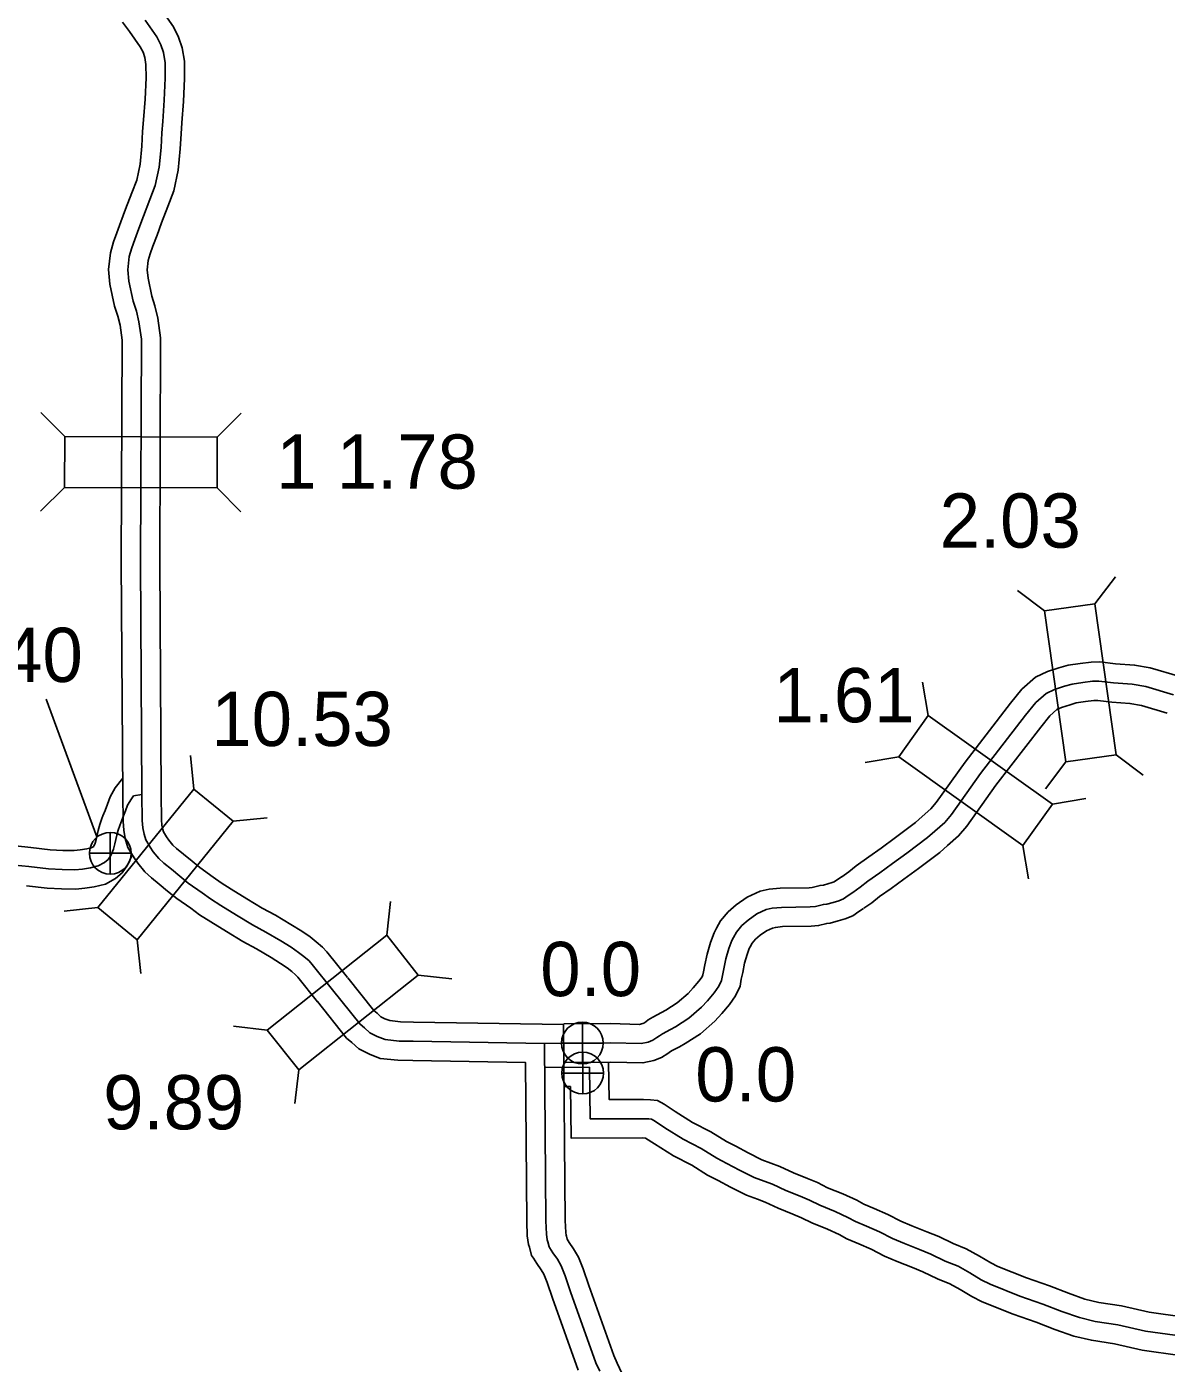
# Model space of a CAD drawing. Extents: x -83719 to 153526, y -11835 to 11446.
# Drawn here: x -2013.5 to -1717.5, y 1861.1 to 2208 of the extents above; entities that cross this region are included whole.
import ezdxf

# ---------------------------------------------------------------- set-up
doc = ezdxf.new("R2010")
doc.units = 0
for name, color, linetype in [('Level 10', 7, 'Continuous'), ('Level 11', 7, 'Continuous'), ('Level 20', 7, 'Continuous'), ('Level 25', 7, 'Continuous'), ('Level 26', 7, 'Continuous'), ('Level 58', 7, 'Continuous'), ('Level 59', 7, 'Continuous')]:
    doc.layers.add(name, color=color, linetype=linetype)

msp = doc.modelspace()

# ---------------------------------------------------------------- linework, layer by layer
at = {"layer": 'Level 10'}
for points in [[(-1978.66, 2212.67), (-1975.38, 2207.95), (-1974.03, 2205.31), (-1973.07, 2202.54), (-1972.5, 2199.05), (-1972.48, 2194.56), (-1972.74, 2188.64), (-1973.17, 2183.08), (-1973.39, 2180.2), (-1973.58, 2176.3), (-1974.14, 2170.79), (-1975.26, 2165.4), (-1976.79, 2161.37), (-1978.44, 2157.12), (-1979.62, 2153.9), (-1980.67, 2151.06), (-1981.41, 2149.05), (-1981.9, 2147.37), (-1982.18, 2144.93), (-1981.96, 2142.73), (-1980.98, 2138.1), (-1980.17, 2135.61), (-1979.39, 2132.4), (-1978.69, 2127.29), (-1978.9, 2069.17), (-1978.53, 2008.78), (-1978.45, 2002.2), (-1978.34, 2000.79), (-1978.13, 1999.64), (-1977.96, 1999.05), (-1977.19, 1997.79), (-1976.58, 1996.9), (-1975.55, 1995.63), (-1974.6, 1994.78), (-1972.71, 1993.24), (-1970.53, 1991.44), (-1968.49, 1989.77), (-1965.02, 1987.34), (-1962.96, 1985.83), (-1960.39, 1984.23), (-1956.32, 1981.71), (-1952.36, 1979.27), (-1948.9, 1977.43), (-1944.85, 1975.05), (-1942.01, 1973.28), (-1939.88, 1971.8), (-1938.27, 1970.54), (-1936.67, 1969.14), (-1935.54, 1967.92), (-1930.14, 1961.25)], [(-1988.61, 2209.2), (-1986.73, 2206.76), (-1983.98, 2202.81), (-1983.25, 2201.38), (-1982.8, 2200.07), (-1982.49, 2198.22), (-1982.48, 2194.76), (-1982.73, 2189.24), (-1983.14, 2183.84), (-1983.37, 2180.83), (-1983.56, 2177.05), (-1984.03, 2172.32), (-1984.89, 2168.22), (-1986.13, 2164.95), (-1987.8, 2160.64), (-1989, 2157.37), (-1990.06, 2154.52), (-1990.91, 2152.18), (-1991.74, 2149.37), (-1992.24, 2144.99), (-1991.85, 2141.18), (-1990.66, 2135.52), (-1989.79, 2132.87), (-1989.23, 2130.54), (-1988.7, 2126.63), (-1988.9, 2069.16), (-1988.53, 2008.69), (-1988.44, 2001.77), (-1988.27, 1999.51), (-1987.87, 1997.31), (-1987.18, 1994.97), (-1985.6, 1992.36), (-1984.6, 1990.91), (-1982.82, 1988.72), (-1981.1, 1987.17), (-1979.05, 1985.51), (-1976.88, 1983.71), (-1974.52, 1981.78), (-1970.85, 1979.22), (-1968.56, 1977.54), (-1965.66, 1975.74), (-1961.58, 1973.2), (-1957.33, 1970.59), (-1953.78, 1968.7), (-1950.02, 1966.49), (-1947.52, 1964.94), (-1945.84, 1963.76), (-1944.64, 1962.82), (-1943.64, 1961.95), (-1943.1, 1961.37), (-1937.92, 1954.96)], [(-1714.05, 2039.35), (-1721.72, 2041.64), (-1725.79, 2042.33), (-1730.76, 2042.7), (-1734.83, 2043.16), (-1737.07, 2043.14), (-1739.88, 2042.78), (-1743.07, 2042.33), (-1745.47, 2041.63), (-1748.39, 2040.69), (-1751.53, 2039.23), (-1755.06, 2036.07), (-1757.99, 2032.46), (-1769.81, 2017.16), (-1777.29, 2006.67), (-1778.67, 2005.03), (-1780.96, 2003.02), (-1782.7, 2001.49), (-1787.89, 1997.58), (-1791.58, 1994.87), (-1794.83, 1992.54), (-1798.04, 1990.27), (-1800.02, 1988.69), (-1801.82, 1987.42)], [(-1717.33, 2029.89), (-1724, 2031.88), (-1727.01, 2032.4), (-1731.69, 2032.74), (-1735.35, 2033.16), (-1736.38, 2033.15), (-1738.55, 2032.87), (-1740.96, 2032.53), (-1742.54, 2032.07), (-1744.73, 2031.36), (-1745.97, 2030.79), (-1747.8, 2029.16), (-1750.14, 2026.25), (-1761.78, 2011.2), (-1769.38, 2000.54), (-1771.5, 1998.01), (-1774.37, 1995.5), (-1776.39, 1993.73), (-1781.92, 1989.55), (-1785.71, 1986.78), (-1789.02, 1984.39), (-1792.03, 1982.27), (-1794.02, 1980.68), (-1796.06, 1979.25)], [(-1801.75, 1987.47), (-1802.92, 1986.68), (-1803.77, 1986.11), (-1804.27, 1985.89), (-1805.41, 1985.58), (-1806.59, 1985.25), (-1807.43, 1985.18), (-1809.51, 1984.63), (-1810.27, 1984.57), (-1817.79, 1984.47), (-1820.66, 1984.16), (-1823, 1983.64), (-1826.4, 1982.11), (-1829.2, 1980.1), (-1831.35, 1978.27), (-1833.27, 1975.94), (-1834.34, 1974.09), (-1834.98, 1972.89), (-1835.9, 1970.34), (-1836.79, 1967.33), (-1837.34, 1964.55), (-1837.73, 1962.73), (-1837.86, 1961.99), (-1838.1, 1961.46), (-1838.89, 1960.33), (-1840.39, 1958.56), (-1841.73, 1957.15), (-1844.54, 1954.69), (-1847.54, 1952.76), (-1848.66, 1952.16), (-1850.88, 1951), (-1852.05, 1950.24), (-1852.67, 1949.77), (-1853.18, 1949.44), (-1853.51, 1949.32), (-1854.41, 1949.11), (-1861.74, 1949.3), (-1874, 1949.2)], [(-1796.13, 1979.2), (-1797.35, 1978.37), (-1798.95, 1977.31), (-1800.9, 1976.45), (-1802.75, 1975.94), (-1804.82, 1975.37), (-1805.72, 1975.29), (-1807.82, 1974.73), (-1809.79, 1974.57), (-1817.19, 1974.48), (-1819.04, 1974.28), (-1819.82, 1974.1), (-1821.39, 1973.4), (-1823.03, 1972.23), (-1824.19, 1971.23), (-1825.04, 1970.2), (-1825.6, 1969.23), (-1825.82, 1968.83), (-1826.4, 1967.23), (-1827.07, 1964.95), (-1827.54, 1962.52), (-1827.92, 1960.8), (-1828.23, 1959), (-1829.37, 1956.51), (-1830.95, 1954.22), (-1832.94, 1951.88), (-1834.78, 1949.94), (-1838.51, 1946.67), (-1842.47, 1944.13), (-1843.99, 1943.31), (-1845.82, 1942.36), (-1846.31, 1942.05), (-1846.94, 1941.57), (-1848.62, 1940.48), (-1850.62, 1939.72), (-1853.43, 1939.09), (-1861.82, 1939.3), (-1873.91, 1939.2)], [(-1930.11, 1961.21), (-1923.35, 1952.69), (-1922.44, 1951.97), (-1921.51, 1951.08), (-1920.45, 1950.57), (-1919.19, 1950.07), (-1916.43, 1949.77), (-1913.06, 1949.7), (-1874.07, 1949.08), (-1873.63, 1898.2), (-1873.51, 1895.12), (-1873.4, 1894.35), (-1873.32, 1894.12), (-1873.13, 1893.35), (-1872.63, 1892.51), (-1871.45, 1890.85), (-1870.18, 1888.69), (-1868.93, 1885.62), (-1867.5, 1881.35), (-1861, 1863.12), (-1860.12, 1861.15), (-1858.91, 1858.59)], [(-1937.95, 1955), (-1930.46, 1945.56), (-1929.02, 1944.42), (-1927.26, 1942.74), (-1924.45, 1941.41), (-1921.64, 1940.28), (-1917.07, 1939.78), (-1913.24, 1939.7), (-1883.98, 1939.23), (-1883.62, 1897.97), (-1883.48, 1894.24), (-1883.17, 1892.01), (-1882.91, 1891.25), (-1882.36, 1889.12), (-1881.83, 1888.42), (-1881.03, 1887.06), (-1879.85, 1885.41), (-1879.17, 1884.25), (-1878.31, 1882.14), (-1876.95, 1878.08), (-1870.29, 1859.39)]]:
    msp.add_lwpolyline(points, dxfattribs=at)
at = {"layer": 'Level 11'}
for points in [[(-1988.42, 2013.04), (-1988.48, 2013.03), (-1990.45, 2010.45), (-1991.82, 2008.12), (-1992.47, 2006.24), (-1993.13, 2004.62), (-1993.67, 2003.22), (-1993.95, 2002.51), (-1994.51, 2000.96), (-1994.93, 1999.4), (-1995.44, 1997.05), (-1995.65, 1996.14), (-1995.99, 1995.38), (-1996.05, 1995.3), (-1996.07, 1995.28), (-1996.73, 1994.91), (-1997.88, 1994.62), (-1999.56, 1994.37), (-2001.14, 1994.23), (-2004.09, 1994.26), (-2007.36, 1994.43), (-2012.39, 1995), (-2016.34, 1995.43)], [(-1986.16, 1992.87), (-1987.25, 1990.43), (-1988.65, 1988.43), (-1990.42, 1986.98), (-1993.02, 1985.53), (-1995.93, 1984.8), (-1998.39, 1984.44), (-2000.74, 1984.23), (-2004.39, 1984.26), (-2008.19, 1984.46), (-2013.49, 1985.06)], [(-1862.37, 1939.19), (-1862.25, 1929.61), (-1853.32, 1929.62), (-1851.48, 1929.55), (-1849.64, 1929.31), (-1847.89, 1928.37), (-1845.04, 1926.46), (-1840.57, 1923.65), (-1835.82, 1921.23), (-1831.79, 1918.7), (-1829.33, 1917.46), (-1826.09, 1915.72), (-1822.57, 1913.95), (-1820.21, 1913.09), (-1817.86, 1912.21), (-1814.31, 1910.6), (-1810.71, 1909.1), (-1808.08, 1908.02), (-1805.49, 1906.72), (-1801.57, 1905.15), (-1797.93, 1903.47), (-1796.06, 1902.43), (-1793.42, 1901.31), (-1789.88, 1899.77), (-1786.51, 1898.05), (-1783.63, 1896.85), (-1779.71, 1895.26), (-1776.64, 1894.02), (-1772.93, 1892.2), (-1769.49, 1890.85), (-1766.02, 1888.96), (-1763.14, 1887.19), (-1761.25, 1886.24), (-1753.85, 1883.29), (-1747.86, 1881.21), (-1742.97, 1879.31), (-1738.69, 1877.8), (-1735.07, 1876.94), (-1729.17, 1876.03), (-1722.03, 1874.43), (-1712.8, 1873.11)], [(-1873.7, 1932.95), (-1872.29, 1932.95), (-1872.12, 1919.6), (-1853.49, 1919.62), (-1852.76, 1919.59), (-1850.48, 1918.07), (-1845.51, 1914.95), (-1840.76, 1912.52), (-1836.7, 1909.98), (-1833.95, 1908.59), (-1830.7, 1906.85), (-1826.54, 1904.75), (-1823.68, 1903.71), (-1821.69, 1902.97), (-1818.3, 1901.43), (-1814.54, 1899.86), (-1812.23, 1898.91), (-1809.6, 1897.59), (-1805.52, 1895.96), (-1802.47, 1894.55), (-1800.46, 1893.43), (-1797.36, 1892.12), (-1794.15, 1890.72), (-1790.7, 1888.96), (-1787.43, 1887.6), (-1783.47, 1885.99), (-1780.73, 1884.88), (-1776.96, 1883.03), (-1773.72, 1881.77), (-1771.03, 1880.3), (-1768.02, 1878.45), (-1765.37, 1877.11), (-1757.34, 1873.92), (-1751.31, 1871.82), (-1746.45, 1869.94), (-1741.52, 1868.19), (-1737, 1867.12), (-1731.03, 1866.2), (-1723.83, 1864.58), (-1714.07, 1863.19)]]:
    msp.add_lwpolyline(points, dxfattribs=at)
at = {"layer": 'Level 20'}
for p, q in [((-2003.58, 2101.67), (-2009.78, 2107.92)), ((-1963.98, 2101.53), (-1957.74, 2107.73)), ((-2003.63, 2088.47), (-2009.88, 2082.27)), ((-1964.03, 2088.33), (-1957.83, 2082.09)), ((-1736.06, 2058.26), (-1730.76, 2065.28)), ((-1749.13, 2056.43), (-1756.16, 2061.73)), ((-1779.37, 2029.25), (-1780.82, 2037.93)), ((-1970.06, 2010.15), (-1970.97, 2018.9)), ((-1730.58, 2019.04), (-1723.55, 2013.74)), ((-1787.03, 2018.5), (-1795.71, 2017.05)), ((-1743.65, 2017.21), (-1748.95, 2010.19)), ((-1747.12, 2006.26), (-1738.44, 2007.71)), ((-1959.81, 2001.83), (-1951.05, 2002.74)), ((-1754.79, 1995.51), (-1753.33, 1986.83)), ((-1919.98, 1972.25), (-1918.97, 1980.99)), ((-1995, 1979.39), (-2003.76, 1978.48)), ((-1984.75, 1971.08), (-1983.84, 1962.32)), ((-1911.77, 1961.91), (-1903.03, 1960.9)), ((-1951, 1947.63), (-1959.74, 1948.64)), ((-1942.79, 1937.29), (-1943.8, 1928.55))]:
    msp.add_line(p, q, dxfattribs=at)
for points in [[(-2003.63, 2088.47), (-1964.03, 2088.33), (-1963.98, 2101.53), (-2003.58, 2101.67)], [(-1749.13, 2056.43), (-1743.65, 2017.21), (-1730.58, 2019.04), (-1736.06, 2058.26)], [(-1787.03, 2018.5), (-1754.79, 1995.51), (-1747.12, 2006.26), (-1779.37, 2029.25)], [(-1984.75, 1971.08), (-1959.81, 2001.83), (-1970.06, 2010.15), (-1995, 1979.39)], [(-1919.98, 1972.25), (-1951, 1947.63), (-1942.79, 1937.29), (-1911.77, 1961.91)]]:
    msp.add_lwpolyline(points, close=True, dxfattribs=at)
at = {"layer": 'Level 25'}
msp.add_line((-2008.4, 2033.47), (-1995.26, 1997.81), dxfattribs=at)
at = {"layer": 'Level 26'}
for p, q in [((-1991.77, 1988.1), (-1991.77, 1998.93)), ((-1997.19, 1993.51), (-1986.36, 1993.51)), ((-1869.16, 1938.82), (-1869.16, 1949.66)), ((-1874.57, 1944.24), (-1863.74, 1944.24)), ((-1869.09, 1931.05), (-1869.09, 1941.88)), ((-1874.51, 1936.46), (-1863.68, 1936.46))]:
    msp.add_line(p, q, dxfattribs=at)
for centre in [(-1991.77, 1993.51), (-1869.16, 1944.24), (-1869.09, 1936.46)]:
    msp.add_circle(centre, 5.42, dxfattribs=at)
at = {"layer": 'Level 59'}
for points in [[(-1982.69, 2209.72), (-1979.68, 2205.38), (-1978.64, 2203.34), (-1977.94, 2201.31), (-1977.5, 2198.64), (-1977.48, 2194.66), (-1977.74, 2188.94), (-1978.15, 2183.46), (-1978.38, 2180.52), (-1978.57, 2176.67), (-1979.09, 2171.56), (-1980.07, 2166.81), (-1981.46, 2163.16), (-1983.12, 2158.88), (-1984.31, 2155.63), (-1985.37, 2152.79), (-1986.16, 2150.61), (-1986.82, 2148.37), (-1987.21, 2144.96), (-1986.9, 2141.95), (-1985.82, 2136.81), (-1984.98, 2134.24), (-1984.31, 2131.47), (-1983.69, 2126.96), (-1983.9, 2069.17), (-1983.53, 2008.74), (-1983.45, 2001.99), (-1983.31, 2000.15), (-1983, 1998.48), (-1982.57, 1997.01), (-1981.39, 1995.07), (-1980.59, 1993.9), (-1979.19, 1992.17), (-1977.85, 1990.97), (-1975.88, 1989.37), (-1973.71, 1987.57), (-1971.5, 1985.78), (-1967.93, 1983.28), (-1965.76, 1981.68), (-1963.02, 1979.99), (-1958.95, 1977.46), (-1954.84, 1974.93), (-1951.34, 1973.07), (-1947.43, 1970.77), (-1944.76, 1969.11), (-1942.86, 1967.78), (-1941.46, 1966.68), (-1940.15, 1965.55), (-1939.32, 1964.65), (-1934.03, 1958.1)], [(-1715.69, 2034.62), (-1722.86, 2036.76), (-1726.4, 2037.36), (-1731.23, 2037.72), (-1735.09, 2038.16), (-1736.72, 2038.14), (-1739.22, 2037.82), (-1742.01, 2037.43), (-1744, 2036.85), (-1746.56, 2036.03), (-1748.75, 2035.01), (-1751.43, 2032.62), (-1754.07, 2029.36), (-1765.8, 2014.18), (-1773.33, 2003.6), (-1775.08, 2001.52), (-1777.66, 1999.26), (-1779.55, 1997.61), (-1784.91, 1993.56), (-1788.65, 1990.83), (-1791.92, 1988.47), (-1795.04, 1986.27), (-1797.02, 1984.69), (-1798.94, 1983.33)], [(-1983.53, 2008.74), (-1985.73, 2008.4), (-1986.29, 2007.66), (-1987.26, 2006.02), (-1987.79, 2004.48), (-1988.48, 2002.77), (-1989.01, 2001.4), (-1989.27, 2000.73), (-1989.74, 1999.46), (-1990.07, 1998.22), (-1990.56, 1995.95), (-1990.89, 1994.54), (-1991.62, 1992.9), (-1992.35, 1991.86), (-1993.25, 1991.13), (-1994.88, 1990.22), (-1996.91, 1989.71), (-1998.97, 1989.41), (-2000.94, 1989.23), (-2004.24, 1989.26), (-2007.77, 1989.45), (-2012.94, 1990.03), (-2016.57, 1990.42)], [(-1798.94, 1983.33), (-1800.13, 1982.52), (-1801.36, 1981.71), (-1802.59, 1981.17), (-1804.08, 1980.76), (-1805.71, 1980.31), (-1806.57, 1980.23), (-1808.67, 1979.68), (-1810.03, 1979.57), (-1817.49, 1979.47), (-1819.85, 1979.22), (-1821.41, 1978.87), (-1823.9, 1977.75), (-1826.11, 1976.17), (-1827.77, 1974.75), (-1829.15, 1973.07), (-1829.97, 1971.66), (-1830.4, 1970.86), (-1831.15, 1968.78), (-1831.93, 1966.14), (-1832.44, 1963.53), (-1832.82, 1961.76), (-1833.05, 1960.49), (-1833.73, 1958.98), (-1834.92, 1957.27), (-1836.67, 1955.22), (-1838.25, 1953.54), (-1841.53, 1950.68), (-1845, 1948.45), (-1846.33, 1947.73), (-1848.35, 1946.68), (-1849.18, 1946.14), (-1849.81, 1945.67), (-1850.9, 1944.96), (-1852.06, 1944.52), (-1853.92, 1944.1), (-1861.78, 1944.3), (-1879.02, 1944.16)], [(-1934.03, 1958.1), (-1926.9, 1949.12), (-1925.73, 1948.2), (-1924.39, 1946.91), (-1922.45, 1945.99), (-1920.41, 1945.17), (-1916.75, 1944.77), (-1913.15, 1944.7), (-1879.02, 1944.16), (-1878.62, 1898.08), (-1878.5, 1894.68), (-1878.29, 1893.18), (-1878.12, 1892.68), (-1877.77, 1891.35), (-1877.67, 1891.22), (-1876.83, 1889.79), (-1875.65, 1888.13), (-1874.67, 1886.47), (-1873.62, 1883.88), (-1872.22, 1879.72), (-1865.65, 1861.26), (-1864.67, 1859.06)], [(-1879.01, 1937.92), (-1867.36, 1937.98), (-1867.18, 1924.6), (-1853.4, 1924.62), (-1851.9, 1924.57), (-1851.2, 1924.47), (-1850.47, 1924.08), (-1847.76, 1922.27), (-1843.04, 1919.3), (-1838.29, 1916.87), (-1834.25, 1914.34), (-1831.64, 1913.03), (-1828.4, 1911.29), (-1824.55, 1909.35), (-1821.95, 1908.4), (-1819.78, 1907.59), (-1816.3, 1906.02), (-1812.63, 1904.48), (-1810.16, 1903.47), (-1807.55, 1902.15), (-1803.54, 1900.55), (-1800.2, 1899.01), (-1798.26, 1897.93), (-1795.39, 1896.72), (-1792.01, 1895.24), (-1788.61, 1893.5), (-1785.53, 1892.23), (-1781.59, 1890.63), (-1778.69, 1889.45), (-1774.94, 1887.61), (-1771.6, 1886.31), (-1768.53, 1884.63), (-1765.58, 1882.82), (-1763.31, 1881.67), (-1755.6, 1878.6), (-1749.59, 1876.52), (-1744.71, 1874.62), (-1740.1, 1873), (-1736.04, 1872.03), (-1730.1, 1871.11), (-1722.93, 1869.5), (-1713.43, 1868.15)]]:
    msp.add_lwpolyline(points, dxfattribs=at)

# ---------------------------------------------------------------- texts
at = {"layer": 'Level 25'}
for s, p in [('13.40', (-2046.01, 2037.96)), ('0.0', (-1880.1, 1956.43)), ('0.0', (-1839.85, 1929.09))]:
    msp.add_text(s, height=14.08, dxfattribs=at).set_placement(p)
at = {"layer": 'Level 58'}
for s, p in [('1 1.78', (-1948.66, 2088.11)), ('2.03', (-1776.39, 2072.82)), ('1.61', (-1819.57, 2027.5)), ('10.53', (-1965.51, 2021.34)), ('9.89', (-1993.61, 1921.85))]:
    msp.add_text(s, height=14.08, dxfattribs=at).set_placement(p)

doc.saveas('drawing.dxf')
